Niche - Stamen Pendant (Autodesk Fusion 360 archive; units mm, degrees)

design "Stamen" references "Luxe Single Pendant Cordset - 4ft Standard", "Niche - Chief Architect - Luxe Single Pendant Cordset", "Stamen"
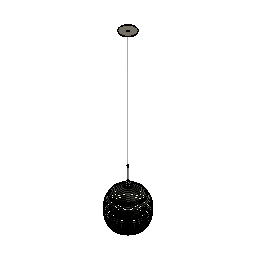
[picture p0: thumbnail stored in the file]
external_derived "ExternalDerived1" bodies "Stamen"
external_derived "ExternalDerived2" bodies "Socket Body", "Shade Ring", "Shade Ring +Collar", "Socket", "Body1", "Metal Strain Relief", "Fabric Cord (1)", "Stem (Threaded)"
align "Align1"
external_derived "ExternalDerived3" bodies "T8-Bulb"
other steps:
derived_base_feature "Derived Base Feature1" bodies "Stamen"
derived_base_feature "Derived Base Feature2" bodies "Socket Body", "Shade Ring", "Shade Ring +Collar", "Socket", "Body1", "Metal Strain Relief", "Fabric Cord (1)", "Stem (Threaded)"
derived_base_feature "Derived Base Feature3" bodies "T8-Bulb"
named bodies: "Stamen", "Socket Body", "Shade Ring", "Shade Ring +Collar", "Socket", "Body1", "Metal Strain Relief", "Fabric Cord (1)", "Stem (Threaded)", "Cap (Threaded)", "5M Set Screw", "T8-Bulb"

design "Luxe Single Pendant Cordset - 4ft Standard" references "Luxe Canopy - Single Pendant Cordset"
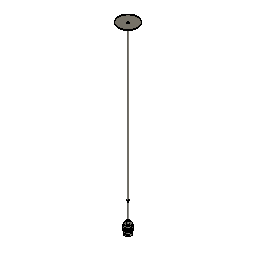
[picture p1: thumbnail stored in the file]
external_derived "ExternalDerived2" bodies "Cap (Threaded)"
move "Move1"
move "Move2"
offset_faces "OffsetFaces1" distance 1051.56
move "Move3"
move "Move4"
move "Move5"
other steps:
derived_base_feature "Derived Base Feature9" bodies "Socket Body", "Shade Ring", "Shade Ring +Collar", "Socket"
derived_base_feature "Derived Base Feature10" bodies "Body1"
derived_base_feature "Derived Base Feature12" bodies "Metal Strain Relief"
derived_base_feature "Derived Base Feature13" bodies "Fabric Cord (1)"
derived_base_feature "Derived Base Feature14" bodies "Stem (Threaded)"
derived_base_feature "Derived Base Feature15" bodies "Cap 9Threaded)", "Cap (Threaded)"
named bodies: "Socket Body", "Shade Ring", "Shade Ring +Collar", "Socket", "Metal Strain Relief", "Fabric Cord (1)", "Stem (Threaded)", "Cap 9Threaded)", "Body1", "Cap (Threaded)", "5M Set Screw"

design "Luxe Canopy - Single Pendant Cordset" references "M5 Set Screw", "Plastic Strain Relief", "Canopy Mounting Bar", "Canopy Mounting Bar Screw", "Luxe Cordset"
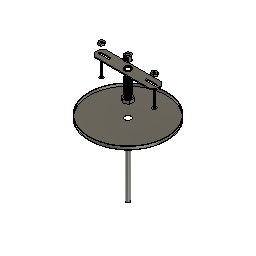
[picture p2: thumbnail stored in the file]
sketch "Sketch1" plane through (0, 0, 0) normal (0, 0, 1) x axis (1, 0, 0)
  circle C1 centre (0, 0) radius 63.5
  point P1 (0, 0)
  point P2 (0, 0)
  coincident P1 P2
  dimension "d1" diameter C1 = 127
extrude "Extrude1" new body sketch "Sketch1" along normal blind 5.08
shell "Shell1" innerThickness 0.762
hole "Hole1" HoleDepth 35.56 HoleDiameter 10.16 TipAngle 118
component_from_bodies "Body->Comp1"
component_insert "Component Insert1"
component_insert "Component Insert2"
component_insert "Component Insert3"
sketch "Sketch2" plane through (0, 0, 0) normal (0, 0, 1) x axis (1, 0, 0)
  circle C1 centre (0, 0) radius 3.175
  point P1 (0, 0)
  point P2 (0, 0)
  coincident P1 P2
  dimension "d8" diameter C1 = 6.35
extrude "Extrude2" new body sketch "Sketch2" along normal blind 127 and against normal blind 127 bodies "Fabric Cord"
component_insert "Component Insert4"
component_insert "Component Insert5"
position "Position1"
sketch "Sketch3" plane through (0, 0, 0.762) normal (0, 0, 1) x axis (-1, 0, 0)
  circle C1 centre (-0.0475, 0.2257) radius 5.08
  circle C2 centre (0, 0) radius 62.738
  circle C3 centre (0, 0) radius 4.826
  concentric C2 C3
  dimension "d13" diameter C3 = 9.652
extrude "Extrude3" new body sketch "Sketch3" profile of C3 along normal blind 25.4 bodies "Threaded Nipple"
shell "Shell2" innerThickness 1.27
thread "Thread1"
sketch "Sketch5" plane through (0, 0, 127) normal (0, 0, 1) x axis (-1, 0, 0)
  line L1 (-6.8191, 3.937) -> (0, 7.874)
  line L2 (-6.8191, -3.937) -> (-6.8191, 3.937)
  line L3 (0, -7.874) -> (-6.8191, -3.937)
  line L4 (6.8191, -3.937) -> (0, -7.874)
  line L5 (6.8191, 3.937) -> (6.8191, -3.937)
  line L6 (0, 7.874) -> (6.8191, 3.937)
  circle C1 centre (0, 0) radius 3.175
  point P2 (0, 0)
  point P9 (0, 0)
  point P3 (0, 7.874)
  coincident P2 P9
  dimension "d20" distance P3 P9 = 7.874
extrude "Extrude4" new body sketch "Sketch5" along normal blind 5.08 bodies "Hex Nut"
move "Move1"
thread "Thread2"
move "Move2" TranslateX 0 TranslateY 0 TranslateZ -55.88
move "Move3" TranslateX 0 TranslateY 0 TranslateZ 60.96
position "Position2"
sketch "Sketch6" plane through (0, 0, 0) normal (0, 0, 1) x axis (1, 0, 0)
  circle C1 centre (0, 0) radius 9.525
  point P1 (0, 0)
  point P2 (0, 0)
  coincident P1 P2
  dimension "d29" diameter C1 = 19.05
extrude "Extrude5" new body sketch "Sketch6" along normal blind 16.129 bodies "Metal Strain Relief"
move "Move4" TranslateX 0 TranslateY 0 TranslateZ -86.36
hole "Hole2" HoleDepth 10.16 HoleDiameter 5.08 TipAngle 118
hole "Hole3" HoleDepth 4.064 HoleDiameter 7.62 TipAngle 180
hole "Hole4" HoleDepth 12.192 HoleDiameter 9.144 TipAngle 180
thread "Thread3" ThreadOffset 0 ThreadLength 6.096
move "Move1" TranslateX 0 TranslateY 0 TranslateZ 68.58
move "Move5" TranslateX 0 TranslateY 0 TranslateZ 138.43
component_insert "Component Insert6"
external_derived "ExternalDerived1" bodies "5M Set Screw"
move "Move6" TranslateX 0 TranslateY 0 TranslateZ -185.42
copy_paste_bodies "CopyPasteBodies1"
move "Move7" TranslateX 0 TranslateY 0 TranslateZ -12.7
offset_faces "OffsetFaces1" distance -152.4
move "Move8"
component_from_bodies "Body->Comp2"
component_from_bodies "Body->Comp3"
component_from_bodies "Body->Comp4"
component_from_bodies "Body->Comp5"
hole "Hole1" HoleDepth 25.4 HoleDiameter 6.35 TipAngle 180
sketch "Sketch7" plane through (0, 0, 0) normal (0, 0, 1) x axis (1, 0, 0)
  line L1 (49.784, 3.9595) -> (52.07, 0)
  line L2 (45.212, 3.9595) -> (49.784, 3.9595)
  line L3 (42.926, 0) -> (45.212, 3.9595)
  line L4 (45.212, -3.9595) -> (42.926, 0)
  line L5 (49.784, -3.9595) -> (45.212, -3.9595)
  line L6 (52.07, 0) -> (49.784, -3.9595)
  point P2 (52.07, 0)
  point P8 (47.498, 0)
  dimension "d63" distance P2 P8 = 4.572
extrude "Extrude6" new body sketch "Sketch7" along normal blind 3.175 bodies "Mounting Hex Nut"
hole "Hole5" HoleDepth 25.4 HoleDiameter 3.81 TipAngle 180
thread "Thread4"
move "Move9"
component_from_bodies "Body->Comp6"
copy_paste "CopyPaste1"
move "Move10"
derived_base_feature "Derived Base Feature3" bodies "Stem (Threaded)", "Cap 9Threaded)"
move "Move11"
component_from_bodies "Body->Comp7"
component_from_bodies "Body->Comp8"
component_from_bodies "Body->Comp9"
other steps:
base_feature "Base Feature1"
base_feature "Base Feature1" bodies "Stem (Threaded)"
base_feature "Base Feature1" bodies "Cap 9Threaded)"
base_feature "Base Feature1" bodies "Fabric Cord"
base_feature "Base Feature1" bodies "Metal Strain Relief"
base_feature "Base Feature1" bodies "Mounting Hex Nut"
base_feature "Base Feature1" bodies "Hex Nut"
base_feature "Base Feature1" bodies "Fabric Cord (1)"
base_feature "Base Feature1" bodies "Threaded Nipple"
derived_base_feature "Derived Base Feature1" bodies "Socket Body", "Shade Ring", "Shade Ring +Collar", "Socket", "Rigid Stem"
derived_base_feature "Derived Base Feature2" bodies "5M Set Screw"
base_feature "Base Feature1" bodies "Fabric Cord", "Fabric Cord (1)"
create_component "CreateComponent1"
remove_body "RemoveBody1"
create_component "CreateComponent2"
remove_body "RemoveBody2"
create_component "CreateComponent3"
remove_body "RemoveBody3"
create_component "CreateComponent4"
remove_body "RemoveBody4"
create_component "CreateComponent5"
remove_body "RemoveBody5"
create_component "CreateComponent6"
remove_body "RemoveBody6"
create_component "CreateComponent7"
remove_body "RemoveBody7"
create_component "CreateComponent8"
remove_body "RemoveBody8"
create_component "CreateComponent9"
remove_body "RemoveBody9"
named bodies: "Fabric Cord", "Threaded Nipple", "Hex Nut", "Metal Strain Relief", "Socket Body", "Shade Ring", "Shade Ring +Collar", "Socket", "Rigid Stem", "5M Set Screw", "Fabric Cord (1)", "Mounting Hex Nut", "Stem (Threaded)", "Cap 9Threaded)"

design "Niche - Chief Architect - Luxe Single Pendant Cordset"
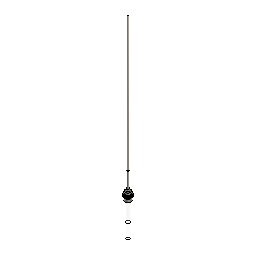
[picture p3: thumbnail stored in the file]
derived_base_feature "Derived Base Feature" bodies "Socket Body", "Shade Ring", "Shade Ring +Collar", "Socket", "Canopy", "Metal Strain Relief", "Fabric Cord (1)", "Stem (Threaded)"
remove_body "RemoveBody1"
remove_body "RemoveBody2"
split "Split1" bodies "Socket Body (1)"
remove_body "RemoveBody3"
align "Align1"
hole "Hole1" HoleDepth 19.05 HoleDiameter 8.89 TipAngle 118
combine "Combine1" bodies "Shade Ring"
split "Split2" bodies "Socket (1)"
remove_body "RemoveBody4"
split "Split3" bodies "Fabric Cord (1) (1)"
remove_body "RemoveBody5"
combine "Combine2" bodies "Socket Body"
align "Align2"
combine "Combine3" bodies "Metal Strain Relief"
sketch "Sketch1" plane through (0, 0, 0) normal (0, 1, 0) x axis (1, 0, 0)
  line L1 (13.1098, 24.9049) -> (-12.2902, 24.9049)
  line L2 (18.1898, 37.1766) -> (18.1898, 29.9849)
  line L3 (-17.3702, 29.9849) -> (-17.3702, 36.7132)
  line L4 (0, 132.969) -> (0, 24.9049)
  arc A1 centre (0, 86.36) radius 46.609 clockwise from (-22.6031, 45.5985) to (23.276, 45.979)
  arc A2 centre (-27.5302, 36.7132) radius 10.16 clockwise from (-22.6031, 45.5985) to (-17.3702, 36.7132)
  arc A3 centre (28.3498, 37.1766) radius 10.16 clockwise from (18.1898, 37.1766) to (23.276, 45.979)
  arc A4 centre (-12.2902, 29.9849) radius 5.08 clockwise from (-12.2902, 24.9049) to (-17.3702, 29.9849)
  arc A5 centre (13.1098, 29.9849) radius 5.08 clockwise from (18.1898, 29.9849) to (13.1098, 24.9049)
  point P5 (18.1898, 43.4469)
  point P3 (-17.3702, 24.9049)
  point P4 (18.1898, 24.9049)
  point P18 (0, 24.9049)
  point P19 (0, 132.969)
  horizontal L1
  vertical L2
  vertical L3
  tangent A1 A2
  tangent L3 A2
  coincident P5 L2
  coincident P5 A1
  tangent L2 A3
  tangent A1 A3
  equal A2 A3
  coincident P3 L1
  coincident P3 L3
  tangent L1 A4
  tangent L3 A4
  coincident P4 L1
  coincident P4 L2
  tangent L1 A5
  tangent L2 A5
  coincident L1 P18
  coincident A1 P19
  perpendicular L1 L4
  dimension "d4" diameter A1 = 93.218
  dimension "d5" distance P3 P4 = 35.56
  dimension "d6" distance P4 P5 = 18.542
  dimension "d7" radius A2 = 10.16
  dimension "d8" radius A4 = 5.08
  dimension "d9" radius A5 = 5.08
revolve "Revolve1" sketch "Sketch1" AlongAngle 360 bodies "G30-Bulb"
move "Move1"
sketch "Sketch2" plane through (0, 0, 0) normal (0, 1, 0) x axis (1, 0, 0)
  line L1 (12.7, 0) -> (-12.7, 0)
  line L2 (12.7, 152.4) -> (12.7, 0)
  line L3 (-12.7, 0) -> (-12.7, 152.4)
  line L4 (0, 165.1) -> (0, 0)
  arc A1 centre (0, 152.4) radius 12.7 clockwise from (-12.7, 152.4) to (12.7, 152.4)
  point P1 (0, 0)
  point P7 (0, 0)
  point P8 (0, 165.1)
  horizontal L1
  vertical L2
  vertical L3
  coincident P1 P7
  midpoint A1 P8
  perpendicular L1 L4
revolve "Revolve2" sketch "Sketch2" AlongAngle 360 bodies "T9-Bulb"
move "Move2"
sketch "Sketch3" plane through (0, 0, 0) normal (0, 1, 0) x axis (1, 0, 0)
  line L1 (12.7, 0) -> (-12.7, 0)
  line L2 (12.7, 254) -> (12.7, 0)
  line L3 (-12.7, 0) -> (-12.7, 254)
  line L4 (0, 266.7) -> (0, 0)
  arc A1 centre (0, 254) radius 12.7 clockwise from (-12.7, 254) to (12.7, 254)
  point P1 (0, 0)
  point P7 (0, 0)
  point P8 (0, 266.7)
  horizontal L1
  vertical L2
  vertical L3
  coincident P1 P7
  midpoint A1 P8
  perpendicular L1 L4
revolve "Revolve3" sketch "Sketch3" AlongAngle 360 bodies "T8-Bulb"
move "Move3"
move "Move4"
move "Move5"
sketch "Sketch4" plane through (0, 0, 0) normal (0, 1, 0) x axis (1, 0, 0)
  line L1 (15.875, -8.763) -> (-15.875, -8.763)
  line L2 (15.875, 22.987) -> (15.875, -8.763)
  line L3 (-15.875, 22.987) -> (15.875, 22.987)
  line L4 (-15.875, -8.763) -> (-15.875, 22.987)
  line L5 (0, 22.987) -> (0, -8.763)
  point P6 (0, -8.763)
  point P7 (0, 22.987)
  point P2 (-15.875, -8.763)
  point P3 (15.875, -8.763)
  point P5 (-15.875, 22.987)
  horizontal L1
  vertical L2
  horizontal L3
  vertical L4
  midpoint L1 P6
  midpoint L3 P7
  dimension "d13" distance P2 P3 = 31.75
  dimension "d14" distance P2 P5 = 31.75
revolve "Revolve4" sketch "Sketch4" AlongAngle 360 bodies "Bulb Extender"
move "Move6"
sketch "Sketch5" plane through (0, 0, 0) normal (0, 1, 0) x axis (1, 0, 0)
  line L1 (-12.7, 35.56) -> (12.7, 35.56)
  line L2 (-12.7, 5.08) -> (-12.7, 35.56)
  line L3 (12.7, 5.08) -> (-12.7, 5.08)
  line L4 (12.7, 35.56) -> (12.7, 5.08)
  line L5 (-12.7, 5.08) -> (12.7, 35.56)
  line L6 (12.7, 5.08) -> (-12.7, 35.56)
  line L7 (0, 35.56) -> (0, 5.08)
  point P6 (0, 20.32)
  point P7 (0, 5.08)
  point P8 (0, 35.56)
  horizontal L1
  perpendicular L1 L2
  parallel L1 L3
  parallel L2 L4
  coincident L5 P6
  coincident L6 P6
  midpoint L3 P7
  midpoint L1 P8
revolve "Revolve5" sketch "Sketch5" AlongAngle 360 bodies "Y-Spliter"
sketch "Sketch6" plane through (0, 0, 0) normal (0, 1, 0) x axis (1, 0, 0)
  line L1 (-55.88, 64.9514) -> (-21.59, 64.9514)
  line L2 (-55.88, 35.7414) -> (-55.88, 64.9514)
  line L3 (-21.59, 35.7414) -> (-55.88, 35.7414)
  line L4 (-21.59, 64.9514) -> (-21.59, 35.7414)
  line L5 (-55.88, 35.7414) -> (-21.59, 64.9514)
  line L6 (-21.59, 35.7414) -> (-55.88, 64.9514)
  line L7 (-38.735, 64.9514) -> (-38.735, 35.7414)
  point P6 (-38.735, 50.3464)
  point P7 (-38.735, 35.7414)
  point P8 (-38.735, 64.9514)
  point P4 (-55.88, 35.7414)
  point P5 (-21.59, 35.7414)
  point P2 (-21.59, 64.9514)
  horizontal L1
  perpendicular L1 L2
  parallel L1 L3
  parallel L2 L4
  coincident L5 P6
  coincident L6 P6
  midpoint L3 P7
  midpoint L1 P8
  dimension "d17" distance P4 P5 = 34.29
  dimension "d18" distance P2 P5 = 29.21
revolve "Revolve6" sketch "Sketch6" AlongAngle 360
chamfer "Chamfer1" distance 7.62
move "Move7"
mirror "Mirror1" mirrorStitchTolerance 0.1016
move "Move8"
combine "Combine4"
move "Move9"
sketch "Sketch7" plane through (0, 0, 0) normal (0, 1, 0) x axis (1, 0, 0)
  line L1 (-15.24, 40.64) -> (-15.24, 48.1816)
  line L2 (12.7, 38.1) -> (-12.7, 38.1)
  line L3 (15.24, 48.1816) -> (15.24, 40.64)
  line L4 (0, 100.1623) -> (0, 38.1)
  arc A1 centre (0, 76.2) radius 23.9623 clockwise from (-19.7282, 62.5988) to (19.7282, 62.5988)
  arc A2 centre (-40.64, 48.1816) radius 25.4 clockwise from (-19.7282, 62.5988) to (-15.24, 48.1816)
  arc A3 centre (40.64, 48.1816) radius 25.4 clockwise from (15.24, 48.1816) to (19.7282, 62.5988)
  arc A4 centre (-12.7, 40.64) radius 2.54 clockwise from (-12.7, 38.1) to (-15.24, 40.64)
  arc A5 centre (12.7, 40.64) radius 2.54 clockwise from (15.24, 40.64) to (12.7, 38.1)
  point P15 (0, 38.1)
  point P16 (0, 100.1623)
  parallel L1 L3
  tangent A1 A2
  tangent L1 A2
  tangent A1 A3
  tangent L3 A3
  tangent L1 A4
  tangent L2 A4
  tangent L2 A5
  tangent L3 A5
  midpoint L2 P15
  midpoint A1 P16
  perpendicular L2 L4
  dimension "d23" radius A2 = 25.4
  dimension "d24" radius A3 = 25.4
  dimension "d25" radius A4 = 2.54
  dimension "d26" radius A5 = 2.54
revolve "Revolve7" sketch "Sketch7" AlongAngle 360 bodies "A15-Bulb"
move "Move10"
copy_paste_bodies "CopyPasteBodies1"
copy_paste_bodies "CopyPasteBodies2"
move "Move11"
mirror "Mirror2" mirrorStitchTolerance 0.1016 bodies "A15-Bulb (1) (1)"
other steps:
base_feature "Base Feature1" bodies "Y-Spliter", "Bulb Extender", "Y-Spliter (1)", "Bulb Extender (1)"
base_feature "Base Feature2" bodies "A15-Bulb", "A15-Bulb (1)"
named bodies: "Socket Body", "Shade Ring", "Shade Ring +Collar", "Socket", "Canopy", "Metal Strain Relief", "Fabric Cord (1)", "Stem (Threaded)", "Adapter", "5M Set Screw", "Body1 (1)", "Socket Body (1)", "Socket (1)", "Fabric Cord (1) (1)", "G30-Bulb", "T9-Bulb", "T8-Bulb", "Bulb Extender", "Y-Spliter", "A15-Bulb", "Y-Spliter (1)", "Bulb Extender (1)", "A15-Bulb (1)", "A15-Bulb (1) (1)"

design "M5 Set Screw"
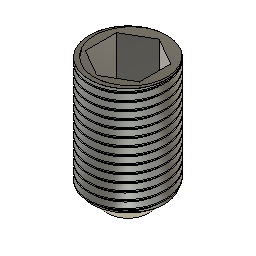
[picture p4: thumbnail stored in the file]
sketch "Sketch1" plane through (0, 0, 0) normal (0, 0, 1) x axis (1, 0, 0)
  circle C1 centre (0, 0) radius 2.5
  point P1 (0, 0)
  point P2 (0, 0)
  coincident P1 P2
  dimension "d1" diameter C1 = 5
extrude "Extrude1" new body sketch "Sketch1" along normal blind 8
sketch "Sketch2" plane through (0, 0, 8) normal (0, 0, 1) x axis (-1, 0, 0)
  line L1 (-1.7321, 1) -> (0, 2)
  line L2 (-1.7321, -1) -> (-1.7321, 1)
  line L3 (0, -2) -> (-1.7321, -1)
  line L4 (1.7321, -1) -> (0, -2)
  line L5 (1.7321, 1) -> (1.7321, -1)
  line L6 (0, 2) -> (1.7321, 1)
  circle C1 centre (0, 0) radius 2.5
  point P2 (0, 0)
  point P9 (0, 0)
  coincident P2 P9
extrude "Extrude2" cut sketch "Sketch2" profile of L1 L2 L3 L4 L5 L6 against normal blind 3
thread "Thread1" ThreadOffset 0.99 ThreadLength 7
chamfer "Chamfer1" distance 1.15

design "Luxe Cordset" references "M5 Set Screw"
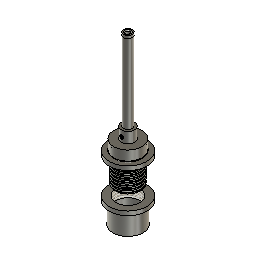
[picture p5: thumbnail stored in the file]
sketch "Sketch1" plane through (0, 0, 0) normal (0, 0, 1) x axis (1, 0, 0)
  circle C1 centre (0, 0) radius 20.6
  point P1 (0, 0)
  point P2 (0, 0)
  coincident P1 P2
  dimension "d11" diameter C1 = 41.2
extrude "Extrude1" new body sketch "Sketch1" along normal blind 14 bodies "Socket Body"
sketch "Sketch2" plane through (0, 0, 14) normal (0, 0, 1) x axis (-1, 0, 0)
  circle C1 centre (0, 0) radius 20.6
  circle C2 centre (0, 0) radius 9.6
  concentric C1 C2
  dimension "d3" diameter C2 = 19.2
extrude "Extrude2" add sketch "Sketch2" profile of C2 along normal blind 15.75
sketch "Sketch3" plane through (0, 0, 29.75) normal (0, 0, 1) x axis (-1, 0, 0)
  circle C1 centre (0, 0) radius 9.6
  circle C2 centre (0, 0) radius 5.75
  concentric C1 C2
  dimension "d6" diameter C2 = 11.5
extrude "Extrude3" new body sketch "Sketch3" profile of C2 along normal blind 114 bodies "Rigid Stem"
move "Move1"
sketch "Sketch4" plane through (0, 0, 203.75) normal (0, 0, 1) x axis (-1, 0, 0)
  circle C1 centre (0, 0) radius 5.75
  circle C2 centre (0, 0) radius 27.5
  dimension "d10" diameter C2 = 55
extrude "Extrude4" new body sketch "Sketch4" profile of C2 along normal blind 6 bodies "Shade Ring"
hole "Hole1" HoleDepth 25 HoleDiameter 42.75 TipAngle 118
sketch "Sketch5" plane through (0, 0, 0) normal (0, 0, 1) x axis (1, 0, 0)
  circle C1 centre (0, 0) radius 22
  point P1 (0, 0)
  point P2 (0, 0)
  coincident P1 P2
  dimension "d18" diameter C1 = 44
move "Move2"
copy_paste_bodies "CopyPasteBodies1"
move "Move3"
sketch "Sketch6" plane through (0, 0, 60) normal (0, 0, -1) x axis (1, 0, 0)
  circle C1 centre (0, 0) radius 20.6
  circle C2 centre (0, 0) radius 21.375
  circle C3 centre (0, 0) radius 20
  concentric C1 C2
  concentric C1 C3
  dimension "d21" diameter C2 = 42.75
  dimension "d24" diameter C3 = 40
cylinder_primitive "CylinderPrimitive1" Height 8 Diameter 42.75
thread "Thread1"
thread "Thread3"
hole "Hole2" HoleDepth 18 HoleDiameter 39 TipAngle 180
move "Move4"
move "Move5"
move "Move6"
hole "Hole3" HoleDepth 114 HoleDiameter 7.6 TipAngle 180
derived_base_feature "Derived Base Feature" bodies "Socket"
move "Move7"
scale "Scale1" ScaleX 1.2 ScaleY 1.2
move "Move8"
sketch "Sketch8" plane through (0, 0, -23.9827) normal (0, 0, -1) x axis (1, 0, 0)
  circle C1 centre (0, -0.036) radius 27.5
  circle C2 centre (0, -0.036) radius 22
  circle C3 centre (0, -0.036) radius 19.5
  dimension "d36" diameter C2 = 44
  dimension "d42" = -2.5
extrude "Extrude7" add sketch "Sketch8" profile of C2 C3 along normal blind 30
offset_faces "OffsetFaces1" distance 2.75
offset_faces "OffsetFaces2" distance -9
thread "Thread2"
move "Move9"
move "Move10"
move "Move11"
scale "Scale2" ScaleZ 1.2
move "Move12"
move "Move13"
move "Move14"
move "Move15"
move "Move16"
split_face "SplitFace1"
move "Move17"
move "Move18"
move "Move19"
move "Move20"
move "Move21"
move "Move22"
move "Move23"
move "Move24"
move "Move25"
move "Move26"
move "Move27"
thread "Thread4"
move "Move28"
move "Move29"
move "Move30"
hole "Hole4" HoleDepth 21 HoleDiameter 39.35 TipAngle 180
hole "Hole5" HoleDepth 9 HoleDiameter 5 TipAngle 180
move "Move31"
move "Move32"
hole "Hole6" HoleDepth 20 HoleDiameter 10 TipAngle 180
move_face "MoveFace3"
move "Move33"
move "Move34"
move "Move35"
move "Move36"
move "Move37"
thread "Thread5" ThreadOffset 0 ThreadLength 6
thread "Thread6" ThreadOffset 0 ThreadLength 6
move "Move38"
move "Move39"
move "Move40"
move "Move41"
component_insert "Component Insert"
thread "Thread7" ThreadOffset 0.5 ThreadLength 5.337
chamfer "Chamfer1" distance 0.5 distance 0.35
sketch "Sketch12" plane through (0, 0, 0) normal (0, 0, 1) x axis (1, 0, 0)
  circle C1 centre (0, 0) radius 6.35
  dimension "d60" diameter C1 = 12.7
extrude "Extrude8" new body sketch "Sketch12" along normal blind 115 bodies "Stem (Threaded)"
hole "Hole7" HoleDepth 115 HoleDiameter 9.65 TipAngle 118
thread "Thread8" ThreadOffset 0 ThreadLength 12.5
thread "Thread9" ThreadOffset 0 ThreadLength 12.5
sketch "Sketch13" plane through (0, 0, 0) normal (0, 0, 1) x axis (1, 0, 0)
  circle C1 centre (0, 0) radius 6.35
  point P1 (0, 0)
  point P2 (0, 0)
  coincident P1 P2
  dimension "d70" diameter C1 = 12.7
extrude "Extrude9" new body sketch "Sketch13" along normal blind 4 bodies "Cap 9Threaded)"
sketch "Sketch14" plane through (0, 0, 4) normal (0, 0, 1) x axis (-1, 0, 0)
  circle C1 centre (0, 0) radius 6.35
  circle C2 centre (0, 0) radius 4.5
  concentric C1 C2
  dimension "d73" diameter C2 = 9
extrude "Extrude10" add sketch "Sketch14" profile of C2 against normal blind 14
thread "Thread10"
hole "Hole8" HoleDepth 115 HoleDiameter 6.5 TipAngle 118 CSDiameter 9 CSAngle 90
move "Move42"
move "Move43"
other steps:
base_feature "Base Feature" bodies "Shade Ring +Collar"
named bodies: "Socket Body", "Shade Ring", "Shade Ring +Collar", "Socket", "Rigid Stem", "Stem (Threaded)", "Cap 9Threaded)"

design "Stamen" references "Niche_Stamen_Single_Pendant"
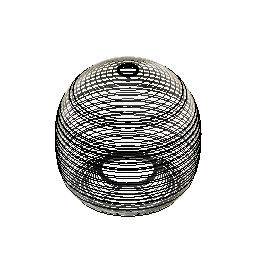
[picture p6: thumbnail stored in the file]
external_derived "ExternalDerived" bodies "Stamen"
fillet "Fillet1" radius 151.13
fillet "Fillet2" radius 149.86
fillet "Fillet3" radius 139.7
fillet "Fillet4" radius 127
fillet "Fillet5" radius 101.6
fillet "Fillet6" radius 17.78
fillet "Fillet7" radius 76.2
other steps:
derived_base_feature "Derived Base Feature" bodies "Stamen"
named bodies: "Stamen"

design "Plastic Strain Relief"
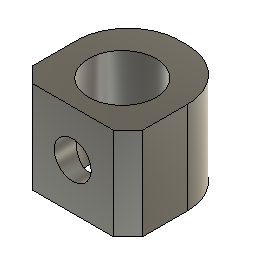
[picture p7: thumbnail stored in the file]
base_feature "Base Feature" bodies "strainrelief"
named bodies: "strainrelief"

design "Niche_Stamen_Single_Pendant"
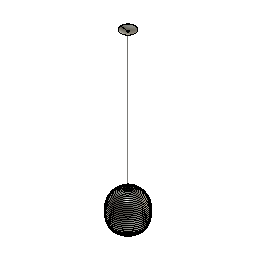
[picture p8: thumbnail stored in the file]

design "Canopy Mounting Bar Screw"
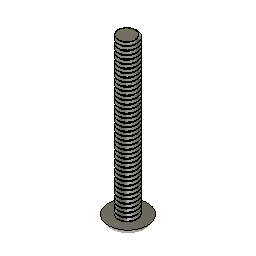
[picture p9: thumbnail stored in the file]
base_feature "Base Feature" bodies "screw1"
named bodies: "screw1"

design "Canopy Mounting Bar"
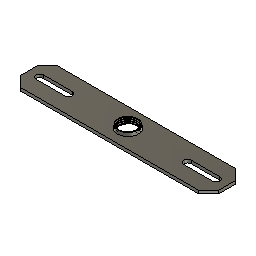
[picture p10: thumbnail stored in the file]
base_feature "Base Feature" bodies "mountingbar"
named bodies: "mountingbar"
